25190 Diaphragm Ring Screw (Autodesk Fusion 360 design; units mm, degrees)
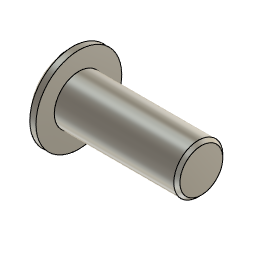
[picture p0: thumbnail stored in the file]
sketch "Main Profile" plane through (0, 0, 0) normal (0, 1, 0) x axis (1, 0, 0)
  line L1 (9.525, 0) -> (0, 0)
  line L2 (9.525, -1.5875) -> (9.525, 0)
  line L3 (1.5875, -1.5875) -> (9.525, -1.5875)
  line L4 (1.5875, -2.7781) -> (1.5875, -1.5875)
  line L5 (1.1906, -2.7781) -> (1.5875, -2.7781)
  arc A1 centre (3.8365, 0) radius 3.8365 clockwise from (1.1906, -2.7781) to (0, 0)
  point P1 (0, 0)
  point P2 (0, 0)
  point P8 (0, 0)
  point P9 (3.8365, 0)
  point P3 (9.525, 0)
  point P4 (9.525, -1.5875)
  point P7 (1.1906, -2.7781)
  coincident P1 P2
  horizontal L1
  perpendicular L1 L2
  perpendicular L2 L3
  perpendicular L3 L4
  perpendicular L4 L5
  coincident P1 P8
  coincident L1 P9
  dimension "d1" distance P3 P4 = 1.5875 (= "( 1 / 16 ) * 1 in")
  dimension "d2" distance P1 P7 = 1.1906 (= "( 3 / 64 ) * 1 in")
  dimension "d5" distance L2 L4 = 7.9375 (= "( 5 / 16 ) * 1 in")
  dimension "d7" distance L3 L5 = 1.1906 (= "( 3 / 64 ) * 1 in")
  dimension "d12" distance P1 L4 = 1.5875
revolve "Revolve1" sketch "Main Profile" AlongAngle 360 bodies "25190 Diaphragm Ring Screw"
work_plane "WorkPlane1"
sketch "Head Profile" plane through (0, 0, 0) normal (-1, 0, 0) x axis (0, 1, 0)
  line L1 (0, 2.7781) -> (0, -2.7781)
  line L2 (-0.3969, 2.7496) -> (-0.3969, -2.7496)
  line L3 (0.3969, 2.7496) -> (0.3969, -2.7496)
  circle C1 centre (0, 0) radius 2.7781
  point P3 (0, -2.7781)
  point P4 (0, 2.7781)
  point P1 (0, 0)
  point P5 (-0.3969, -2.7496)
  point P6 (-0.3969, 2.7496)
  point P7 (0.3969, -2.7496)
  point P8 (0.3969, 2.7496)
  coincident C1 P3
  coincident C1 P4
  vertical L1
  coincident P1 L1
  coincident C1 P5
  coincident C1 P6
  vertical L2
  coincident C1 P7
  coincident C1 P8
  parallel L1 L3
  symmetric L1 L2 L3
  dimension "d9" distance L2 L3 = 0.7937 (= "( 1 / 32 ) * 1 in")
extrude "Extrude1" cut sketch "Head Profile" profile of C1 L2 L3 against normal blind 1.1906 (magnitude of "( -3 / 64 ) * 1 in")
chamfer "Chamfer1" distance 0.1984 (= "( 1 / 128 ) * 1 in")
named bodies: "25190 Diaphragm Ring Screw"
